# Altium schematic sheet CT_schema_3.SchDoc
size 283 x 147 mm
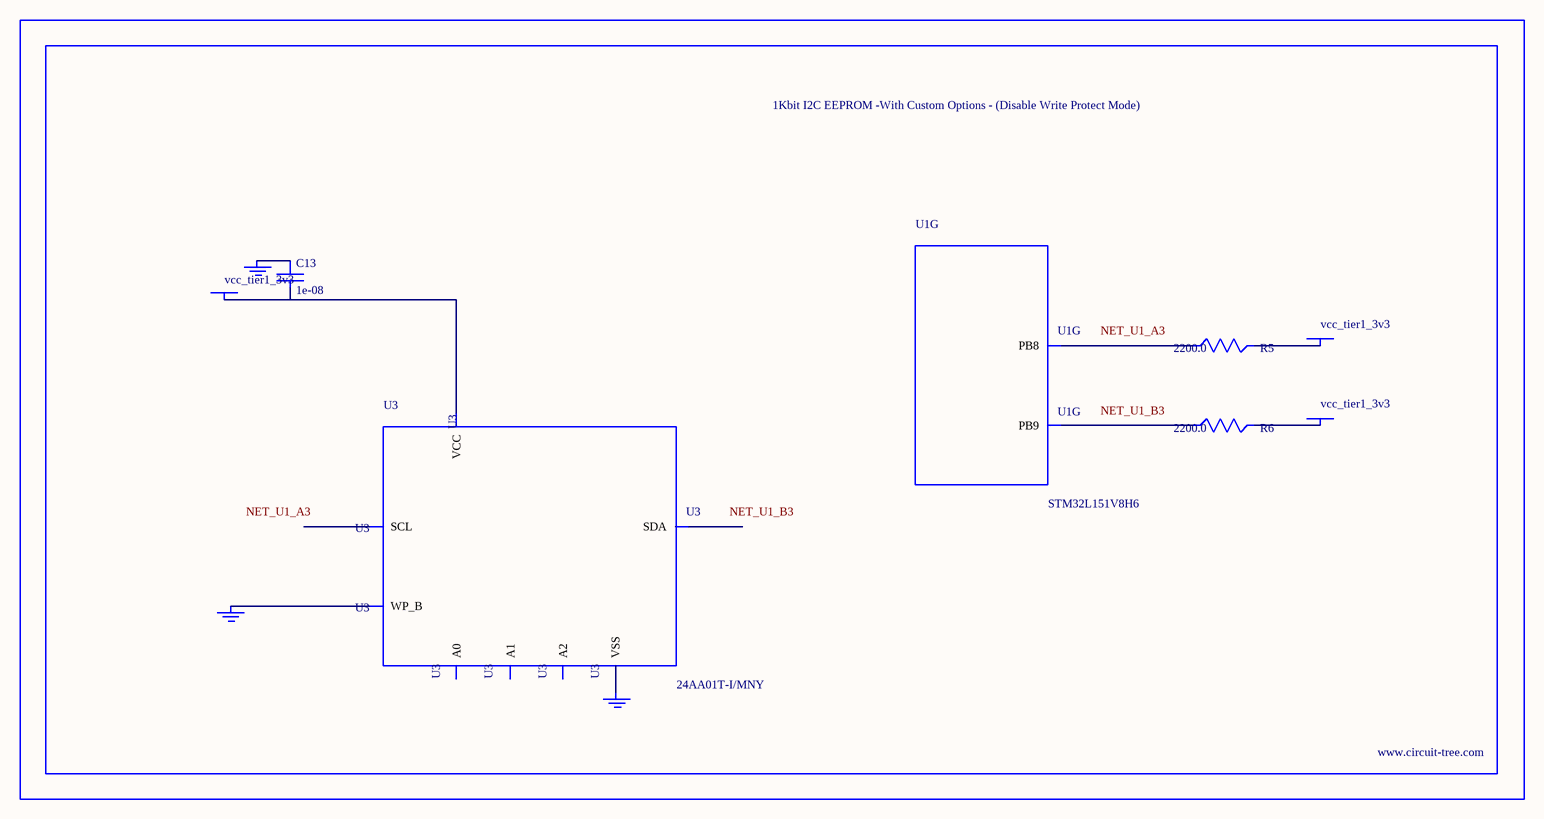
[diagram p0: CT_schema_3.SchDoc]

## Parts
BORDER2  (no value)
C13  1e-08  [C0402]
GND_INSTANCE_2_0  (no value)
GND_INSTANCE_2_1  (no value)
GND_INSTANCE_2_2  (no value)
POWER_INSTANCE_2_0  vcc_tier1_3v3
POWER_INSTANCE_2_1  vcc_tier1_3v3
POWER_INSTANCE_2_2  vcc_tier1_3v3
R5  2200.0  [R0603]
R6  2200.0  [R0603]
U1  STM32L151V8H6  [UFBGA100]  (part G of 9)
U3  24AA01T-I/MNY  [TDFN-8/6MM]

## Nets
NetC13_1: C13.1 GND_INSTANCE_2_1.0(GND)
NetC13_2: C13.2 POWER_INSTANCE_2_0.0(PWR) U3.8(VCC)
NetGND_INSTANCE_2_0_0: GND_INSTANCE_2_0.0(GND) U3.7(WP_B)
NetGND_INSTANCE_2_2_0: GND_INSTANCE_2_2.0(GND) U3.4(VSS)
NetPOWER_INSTANCE_2_1_0: POWER_INSTANCE_2_1.0(PWR) R5.2
NetPOWER_INSTANCE_2_2_0: POWER_INSTANCE_2_2.0(PWR) R6.2
NetR5_1: R5.1 U1.A3(PB8)
NetR6_1: R6.1 U1.B3(PB9)

Not connected (* = marked no-connect by the designer): U3 1(A0) 2(A1) 3(A2) 5(SDA) 6(SCL)

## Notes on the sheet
- Labels drawn without touching a wire or pin: NET_U1_A3, NET_U1_B3

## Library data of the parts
BORDER2 = BORDER_PAGE2
C13 = C0402C103K3RAC
GND_INSTANCE_2_0-GND_INSTANCE_2_2 = GND
POWER_INSTANCE_2_0-POWER_INSTANCE_2_2 = PWR
R5 R6 = RC0603JR-072K2L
